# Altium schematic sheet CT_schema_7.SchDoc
size 371 x 245 mm
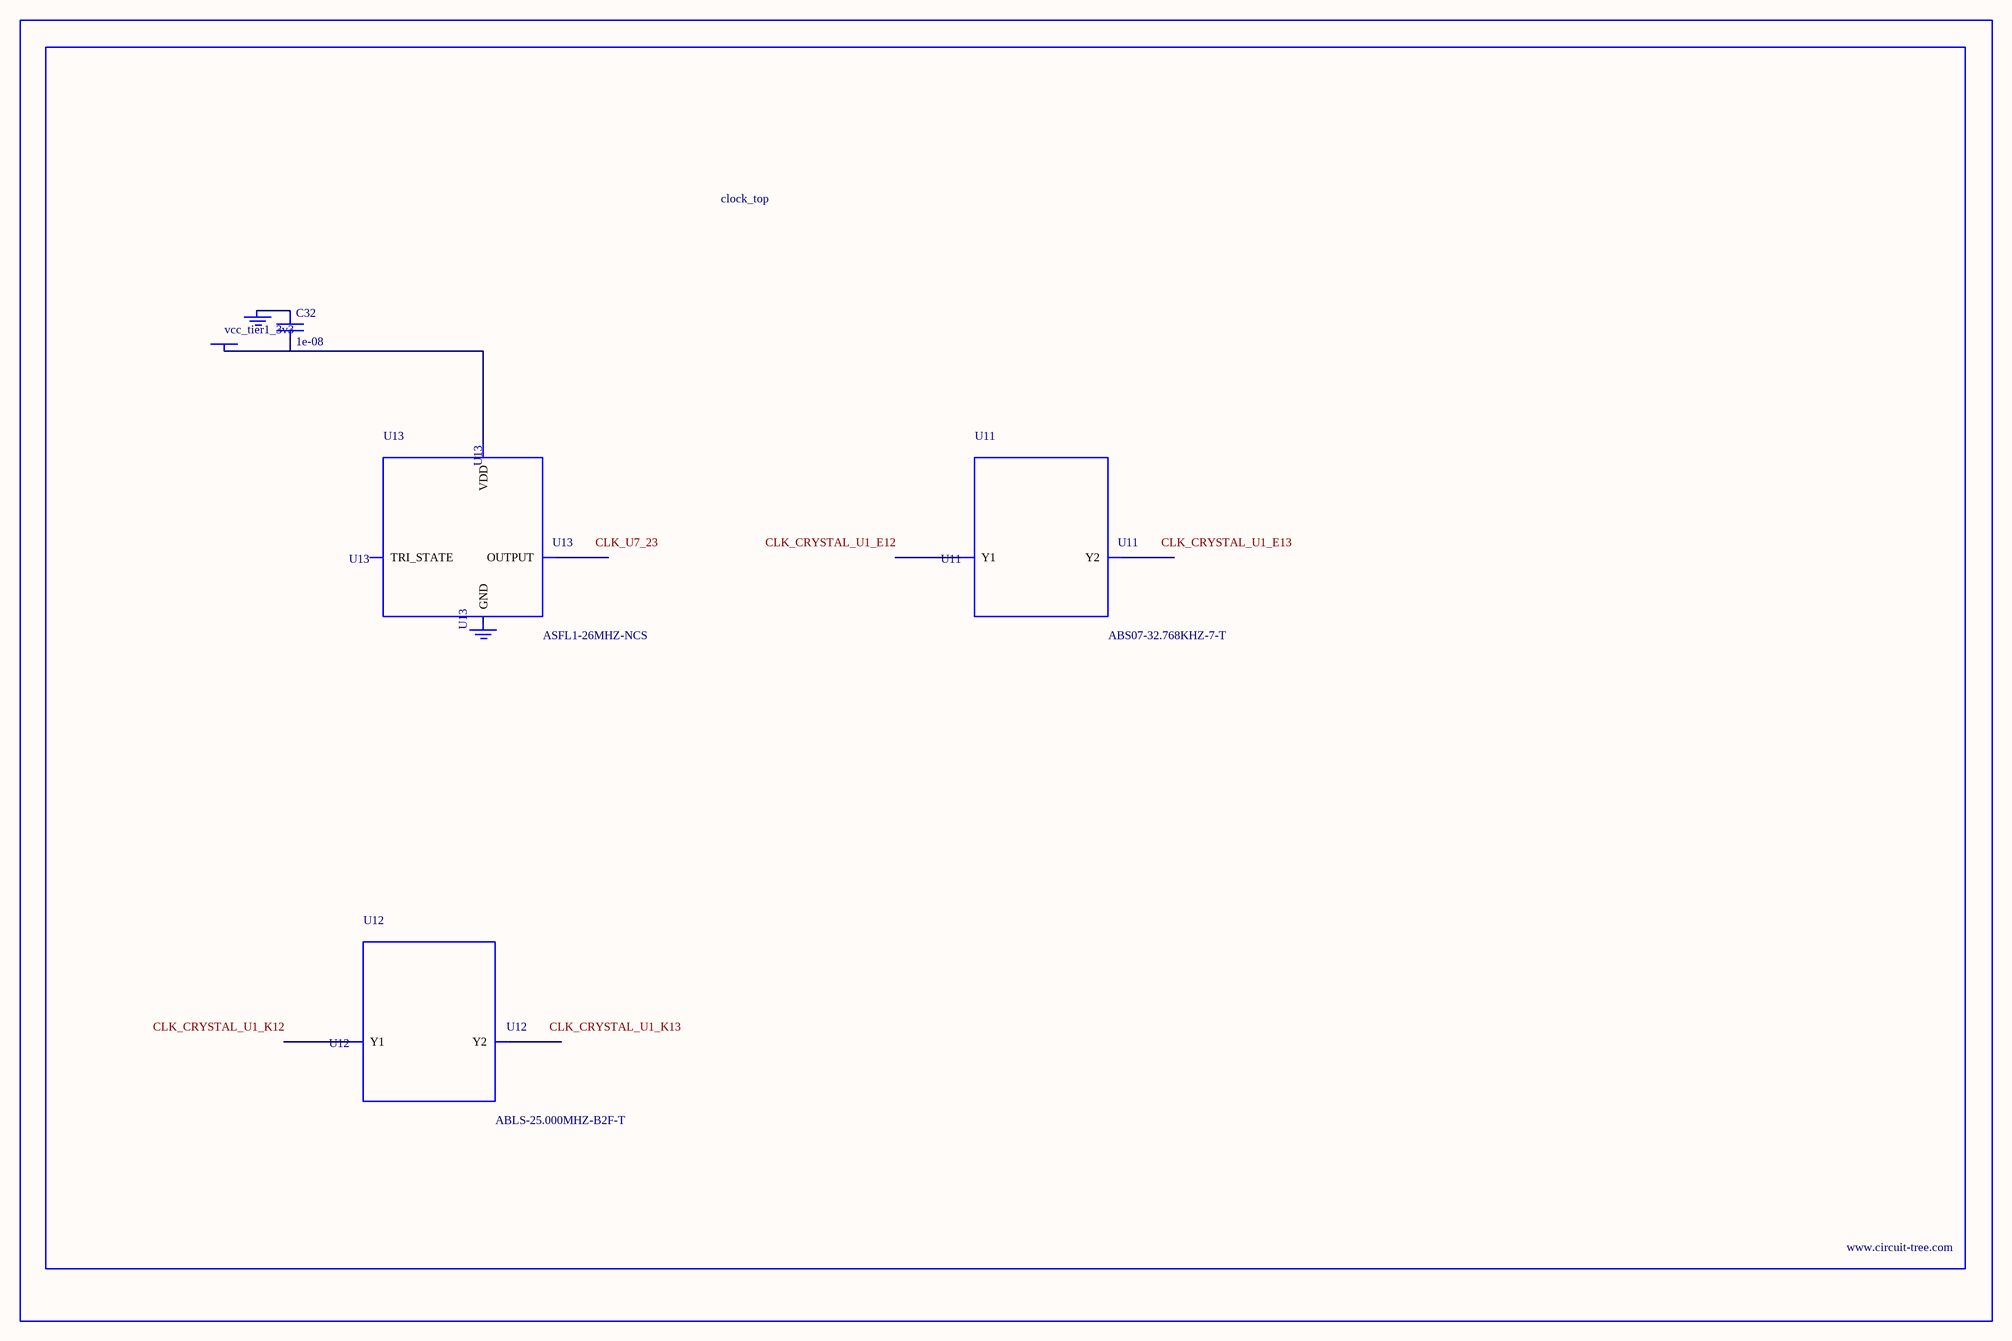
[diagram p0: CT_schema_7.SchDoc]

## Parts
BORDER6  (no value)
C32  1e-08  [C0402]
GND_INSTANCE_6_0  (no value)
GND_INSTANCE_6_1  (no value)
POWER_INSTANCE_6_0  vcc_tier1_3v3
U11  ABS07-32.768KHZ-7-T  [ABS07-32.768KHZ-7-T]
U12  ABLS-25.000MHZ-B2F-T  [ABLS-25.000MHZ-B2F-T]
U13  ASFL1-26MHZ-NCS  [ASFL1]

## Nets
NetC32_1: C32.1 GND_INSTANCE_6_0.0(GND)
NetC32_2: C32.2 POWER_INSTANCE_6_0.0(PWR) U13.4(VDD)

Not connected (* = marked no-connect by the designer): GND_INSTANCE_6_1 0(GND); U11 1(Y1) 2(Y2); U12 1(Y1) 2(Y2); U13 1(TRI_STATE) 2(GND) 3(OUTPUT)

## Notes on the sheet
- Labels drawn without touching a wire or pin: CLK_CRYSTAL_U1_E12, CLK_CRYSTAL_U1_E13, CLK_CRYSTAL_U1_K12, CLK_CRYSTAL_U1_K13, CLK_U7_23

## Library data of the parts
BORDER6 = BORDER_PAGE6
C32 = C0402C103K3RAC
GND_INSTANCE_6_0 GND_INSTANCE_6_1 = GND
POWER_INSTANCE_6_0 = PWR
